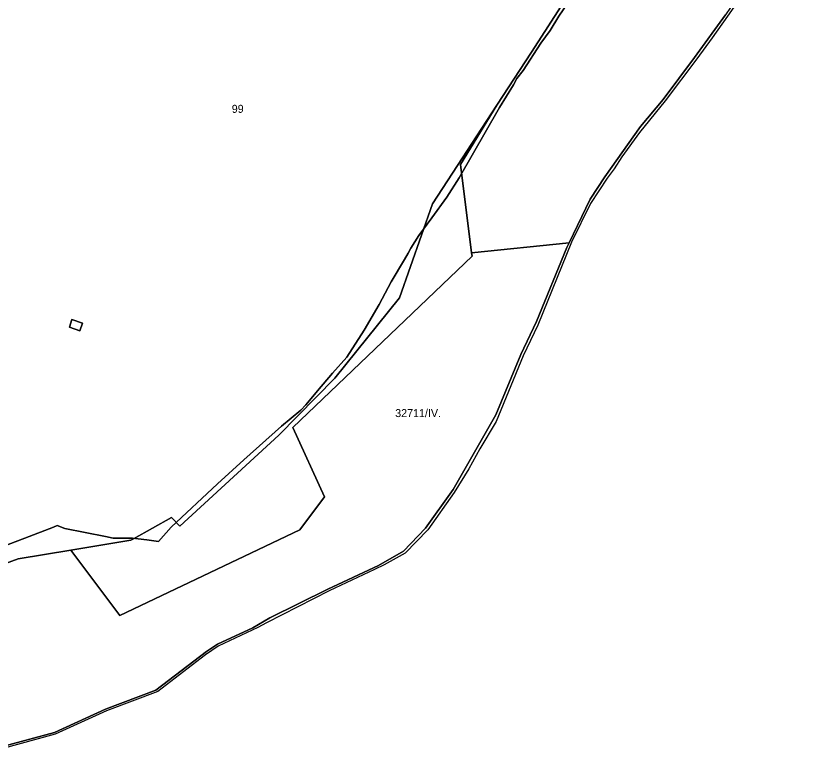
# Model space of a CAD drawing. Extents: x -541351 to -537540, y -1162694 to -1159725.
# Drawn here: x -538281.1 to -537783.8, y -1162554.6 to -1162096.9 of the extents above; entities that cross this region are included whole.
import ezdxf

# ---------------------------------------------------------------- set-up
doc = ezdxf.new("R2010")
doc.units = 0
for name, color, linetype in [('95560013', 7, 'Continuous'), ('95610013', 7, 'Continuous'), ('95620013', 7, 'Continuous'), ('95640013', 7, 'Continuous'), ('95660013', 7, 'Continuous')]:
    doc.layers.add(name, color=color, linetype=linetype)

msp = doc.modelspace()

# ---------------------------------------------------------------- linework, layer by layer
at = {"layer": '95560013'}
msp.add_lwpolyline([(-537837.81, -1162096.24), (-537857.15, -1162122.84), (-537876.73, -1162149.18), (-537890.98, -1162165.98), (-537913.23, -1162197.28), (-537922.33, -1162211.34), (-537935.55, -1162238.66), (-537996.43, -1162244.72), (-538003.43, -1162189.61), (-537980.73, -1162152.69), (-537959.1, -1162119.55), (-537913.59, -1162048.98), (-537796.39, -1162019.36), (-537802.31, -1162014.18), (-537783.76, -1162015.03), (-537790.37, -1162024.85), (-537814.41, -1162061.25), (-537819.11, -1162068.63)], close=True, dxfattribs=at)
msp.add_lwpolyline([(-538334.63, -1162456.04), (-538279.83, -1162435.82), (-538246.94, -1162430.44), (-538216.31, -1162471.24), (-538103.72, -1162417.68), (-538088.29, -1162397.07), (-538108.15, -1162353.88), (-537996.15, -1162246.93), (-537996.43, -1162244.72), (-537935.55, -1162238.66), (-537936.9, -1162241.44), (-537955.85, -1162287.76), (-537965.65, -1162308.25), (-537981.3, -1162346.04), (-538007.88, -1162392.49), (-538025.18, -1162416.67), (-538038.91, -1162431.05), (-538054.68, -1162439.95), (-538086.18, -1162454.76), (-538122.59, -1162472.79), (-538133.14, -1162478.9), (-538155.27, -1162489.2), (-538162.13, -1162493.78), (-538193.8, -1162517.84), (-538225.08, -1162529.67), (-538257.12, -1162544.31), (-538291.24, -1162553.47)], dxfattribs=at)
at = {"layer": '95610013'}
msp.add_lwpolyline([(-538178.66, -1162415.49), (-538116.81, -1162358.63), (-538081.87, -1162323), (-538041.52, -1162272.9), (-538020.92, -1162214.26), (-537980.73, -1162152.69), (-538003.43, -1162189.61), (-537996.43, -1162244.72), (-537996.15, -1162246.93), (-538108.15, -1162353.88), (-538088.29, -1162397.07), (-538103.72, -1162417.68), (-538216.31, -1162471.24), (-538246.94, -1162430.44), (-538209.34, -1162424.28), (-538207.68, -1162423.35), (-538183.91, -1162410.12)], close=True, dxfattribs=at)
at = {"layer": '95620013'}
msp.add_lwpolyline([(-537913.59, -1162048.98), (-537959.1, -1162119.55), (-537980.73, -1162152.69), (-538020.92, -1162214.26), (-538041.52, -1162272.9), (-538081.87, -1162323), (-538116.81, -1162358.63), (-538178.66, -1162415.49), (-538183.91, -1162410.12), (-538207.68, -1162423.35), (-538209.34, -1162424.28), (-538246.94, -1162430.44), (-538279.83, -1162435.82), (-538334.63, -1162456.04)], dxfattribs=at)
for points in [[(-538241.27, -1162293.44), (-538239.54, -1162288.73), (-538246.13, -1162286.48), (-538247.72, -1162291.23)], [(-538241.27, -1162293.44), (-538247.72, -1162291.23), (-538246.13, -1162286.48), (-538239.54, -1162288.73)]]:
    msp.add_lwpolyline(points, close=True, dxfattribs=at)
at = {"layer": '95640013'}
for points in [[(-537827.3, -1162083.56), (-537836.59, -1162097.02), (-537846.19, -1162110.58), (-537855.72, -1162123.63), (-537875.49, -1162149.88), (-537891.57, -1162169.65), (-537902.65, -1162184.82), (-537907.5, -1162192.31), (-537911.86, -1162198.11), (-537922.18, -1162213.99), (-537933.96, -1162238.09), (-537955.18, -1162289.88), (-537964.3, -1162309.05), (-537981.13, -1162350.15), (-537991.36, -1162367.12), (-537998.23, -1162379.68), (-538007.3, -1162394.44), (-538023.79, -1162417.82), (-538037.95, -1162432.29), (-538051.04, -1162439.71), (-538057.18, -1162442.45), (-538085.43, -1162455.94), (-538124.67, -1162475.77), (-538129.94, -1162478.83), (-538154.81, -1162490.46), (-538162.69, -1162495.9), (-538192.39, -1162518.69), (-538224.57, -1162530.82), (-538256.67, -1162545.39), (-538290.71, -1162554.65)], [(-538291.24, -1162553.47), (-538257.12, -1162544.31), (-538225.08, -1162529.67), (-538193.8, -1162517.84), (-538162.13, -1162493.78), (-538155.27, -1162489.2), (-538133.14, -1162478.9), (-538122.59, -1162472.79), (-538086.18, -1162454.76), (-538054.68, -1162439.95), (-538038.91, -1162431.05), (-538025.18, -1162416.67), (-538007.88, -1162392.49), (-537981.3, -1162346.04), (-537965.65, -1162308.25), (-537955.85, -1162287.76), (-537936.9, -1162241.44), (-537935.55, -1162238.66), (-537922.33, -1162211.34), (-537913.23, -1162197.28), (-537890.98, -1162165.98), (-537876.73, -1162149.18), (-537857.15, -1162122.84), (-537837.81, -1162096.24)]]:
    msp.add_lwpolyline(points, dxfattribs=at)
at = {"layer": '95660013'}
for points in [[(-538299.37, -1162432), (-538275.5, -1162423), (-538257.62, -1162416), (-538255.31, -1162415), (-538250.62, -1162417), (-538225.12, -1162422), (-538220.31, -1162423), (-538208.31, -1162423), (-538199.37, -1162424), (-538192.12, -1162425), (-538184.12, -1162416), (-538155.31, -1162389), (-538138.81, -1162374), (-538115.19, -1162353), (-538103.12, -1162343), (-538100.1, -1162339.67), (-538097.69, -1162337), (-538092.81, -1162331), (-538083.37, -1162320), (-538074.5, -1162310), (-538063.62, -1162293), (-538054.31, -1162277), (-538046.69, -1162263), (-538038.31, -1162249), (-538036.12, -1162245), (-538034.5, -1162242), (-538029.5, -1162234), (-538021.37, -1162223), (-538012, -1162210), (-538004.31, -1162198), (-537979.12, -1162154), (-537970.31, -1162140), (-537968.31, -1162136), (-537964.19, -1162131), (-537953.31, -1162114), (-537947.37, -1162106), (-537941.87, -1162097), (-537925.62, -1162073)], [(-537925.62, -1162073), (-537941.87, -1162097), (-537947.37, -1162106), (-537953.31, -1162114), (-537964.19, -1162131), (-537968.31, -1162136), (-537970.31, -1162140), (-537979.12, -1162154), (-538004.31, -1162198), (-538012, -1162210), (-538021.37, -1162223), (-538029.5, -1162234), (-538034.5, -1162242), (-538036.12, -1162245), (-538038.31, -1162249), (-538046.69, -1162263), (-538054.31, -1162277), (-538063.62, -1162293), (-538074.5, -1162310), (-538083.37, -1162320), (-538092.81, -1162331), (-538097.69, -1162337), (-538100.1, -1162339.67), (-538103.12, -1162343), (-538115.19, -1162353), (-538138.81, -1162374), (-538155.31, -1162389), (-538184.12, -1162416), (-538192.12, -1162425), (-538199.37, -1162424), (-538208.31, -1162423), (-538220.31, -1162423), (-538225.12, -1162422), (-538250.62, -1162417), (-538255.31, -1162415), (-538257.62, -1162416), (-538275.5, -1162423), (-538299.37, -1162432)], [(-537827.3, -1162083.56), (-537836.59, -1162097.02), (-537846.19, -1162110.58), (-537855.72, -1162123.63), (-537875.49, -1162149.88), (-537891.57, -1162169.65), (-537902.65, -1162184.82), (-537907.5, -1162192.31), (-537911.86, -1162198.11), (-537922.18, -1162213.99), (-537933.96, -1162238.09), (-537955.18, -1162289.88), (-537964.3, -1162309.05), (-537981.13, -1162350.15), (-537991.36, -1162367.12), (-537998.23, -1162379.68), (-538007.3, -1162394.44), (-538023.79, -1162417.82), (-538037.95, -1162432.29), (-538051.04, -1162439.71), (-538057.18, -1162442.45), (-538085.43, -1162455.94), (-538124.67, -1162475.77), (-538129.94, -1162478.83), (-538154.81, -1162490.46), (-538162.69, -1162495.9), (-538192.39, -1162518.69), (-538224.57, -1162530.82), (-538256.67, -1162545.39), (-538290.71, -1162554.65)]]:
    msp.add_lwpolyline(points, dxfattribs=at)

# ---------------------------------------------------------------- texts
for s, rotation, p in [('99', 0, (-538146.3, -1162157.4)), ('32711/IV.', 360, (-538044.2, -1162347.38))]:
    msp.add_text(s, height=5, rotation=rotation, dxfattribs=at).set_placement(p)

doc.saveas('drawing.dxf')
